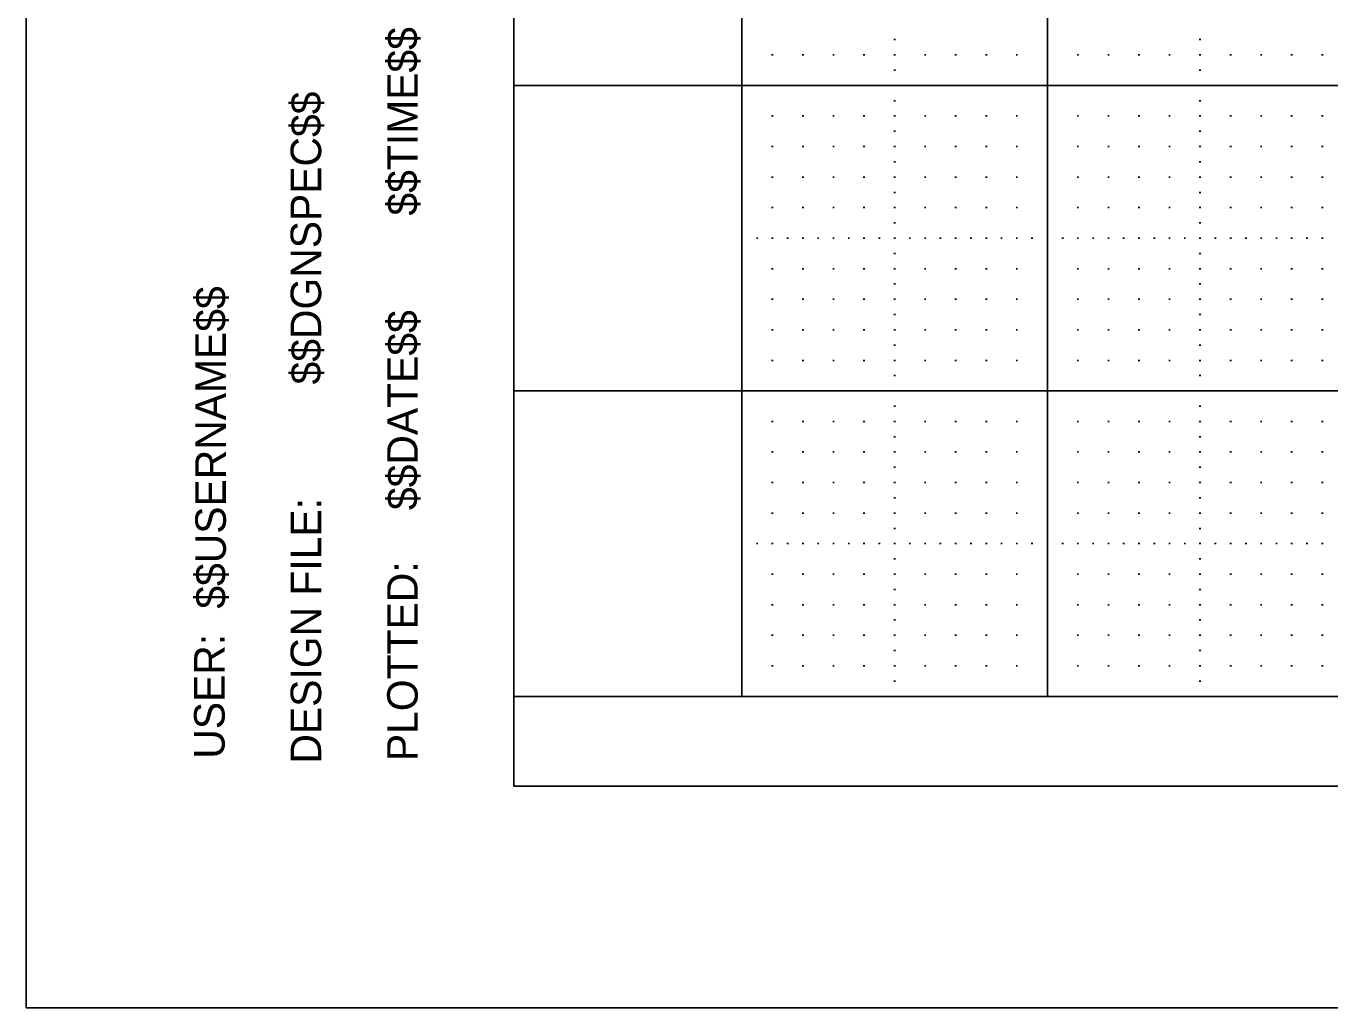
# Model space of a CAD drawing. Extents: x -1.6 to 32.7, y -1.7 to 21.9.
# Drawn here: x -1.598 to 2.67, y -0.727 to 2.487 of the extents above; entities that cross this region are included whole.
import ezdxf

# ---------------------------------------------------------------- set-up
doc = ezdxf.new("R2010")
doc.units = 0
for name, color, linetype in [('Level 1', 7, 'Continuous'), ('Level 4', 7, 'Continuous'), ('Level 5', 7, 'Continuous'), ('Level 63', 7, 'Continuous'), ('R_Border_Dark', 7, 'Continuous')]:
    doc.layers.add(name, color=color, linetype=linetype)

msp = doc.modelspace()

# ---------------------------------------------------------------- linework, layer by layer
at = {"layer": 'Level 1'}
for p, q in [((-0.001, -0.001), (-0.001, 20.545)), ((31.617, -0.001), (-0.001, -0.001))]:
    msp.add_line(p, q, dxfattribs=at)
msp.add_lwpolyline([(0.745, 11.3072), (30.745, 11.3072), (30.745, 0.293), (0.745, 0.293)], close=True, dxfattribs=at)
at = {"layer": 'Level 4'}
msp.add_line((31.617, 0.293), (-0.001, 0.293), dxfattribs=at)
at = {"layer": 'Level 5'}
for p, q in [((1.2425, 2.443), (1.2475, 2.443)), ((2.2425, 2.443), (2.2475, 2.443)), ((0.8425, 2.393), (0.8475, 2.393)), ((0.9425, 2.393), (0.9475, 2.393)), ((1.0425, 2.393), (1.0475, 2.393)), ((1.1425, 2.393), (1.1475, 2.393)), ((1.2425, 2.393), (1.2475, 2.393)), ((1.3425, 2.393), (1.3475, 2.393)), ((1.4425, 2.393), (1.4475, 2.393)), ((1.5425, 2.393), (1.5475, 2.393)), ((1.6425, 2.393), (1.6475, 2.393)), ((1.8425, 2.393), (1.8475, 2.393)), ((1.9425, 2.393), (1.9475, 2.393)), ((2.0425, 2.393), (2.0475, 2.393)), ((2.1425, 2.393), (2.1475, 2.393)), ((2.2425, 2.393), (2.2475, 2.393)), ((2.3425, 2.393), (2.3475, 2.393)), ((2.4425, 2.393), (2.4475, 2.393)), ((2.5425, 2.393), (2.5475, 2.393)), ((2.6425, 2.393), (2.6475, 2.393)), ((1.2425, 2.343), (1.2475, 2.343)), ((2.2425, 2.343), (2.2475, 2.343)), ((1.2425, 2.243), (1.2475, 2.243)), ((2.2425, 2.243), (2.2475, 2.243)), ((0.8425, 2.193), (0.8475, 2.193)), ((0.9425, 2.193), (0.9475, 2.193)), ((1.0425, 2.193), (1.0475, 2.193)), ((1.1425, 2.193), (1.1475, 2.193)), ((1.2425, 2.193), (1.2475, 2.193)), ((1.3425, 2.193), (1.3475, 2.193)), ((1.4425, 2.193), (1.4475, 2.193)), ((1.5425, 2.193), (1.5475, 2.193)), ((1.6425, 2.193), (1.6475, 2.193)), ((1.8425, 2.193), (1.8475, 2.193)), ((1.9425, 2.193), (1.9475, 2.193)), ((2.0425, 2.193), (2.0475, 2.193)), ((2.1425, 2.193), (2.1475, 2.193)), ((2.2425, 2.193), (2.2475, 2.193)), ((2.3425, 2.193), (2.3475, 2.193)), ((2.4425, 2.193), (2.4475, 2.193)), ((2.5425, 2.193), (2.5475, 2.193)), ((2.6425, 2.193), (2.6475, 2.193)), ((1.2425, 2.143), (1.2475, 2.143)), ((2.2425, 2.143), (2.2475, 2.143)), ((0.8425, 2.093), (0.8475, 2.093)), ((0.9425, 2.093), (0.9475, 2.093)), ((1.0425, 2.093), (1.0475, 2.093)), ((1.1425, 2.093), (1.1475, 2.093)), ((1.2425, 2.093), (1.2475, 2.093)), ((1.3425, 2.093), (1.3475, 2.093)), ((1.4425, 2.093), (1.4475, 2.093)), ((1.5425, 2.093), (1.5475, 2.093)), ((1.6425, 2.093), (1.6475, 2.093)), ((1.8425, 2.093), (1.8475, 2.093)), ((1.9425, 2.093), (1.9475, 2.093)), ((2.0425, 2.093), (2.0475, 2.093)), ((2.1425, 2.093), (2.1475, 2.093)), ((2.2425, 2.093), (2.2475, 2.093)), ((2.3425, 2.093), (2.3475, 2.093)), ((2.4425, 2.093), (2.4475, 2.093)), ((2.5425, 2.093), (2.5475, 2.093)), ((2.6425, 2.093), (2.6475, 2.093)), ((1.2425, 2.043), (1.2475, 2.043)), ((2.2425, 2.043), (2.2475, 2.043)), ((0.8425, 1.993), (0.8475, 1.993)), ((0.9425, 1.993), (0.9475, 1.993)), ((1.0425, 1.993), (1.0475, 1.993)), ((1.1425, 1.993), (1.1475, 1.993)), ((1.2425, 1.993), (1.2475, 1.993)), ((1.3425, 1.993), (1.3475, 1.993)), ((1.4425, 1.993), (1.4475, 1.993)), ((1.5425, 1.993), (1.5475, 1.993)), ((1.6425, 1.993), (1.6475, 1.993)), ((1.8425, 1.993), (1.8475, 1.993)), ((1.9425, 1.993), (1.9475, 1.993)), ((2.0425, 1.993), (2.0475, 1.993)), ((2.1425, 1.993), (2.1475, 1.993)), ((2.2425, 1.993), (2.2475, 1.993)), ((2.3425, 1.993), (2.3475, 1.993)), ((2.4425, 1.993), (2.4475, 1.993)), ((2.5425, 1.993), (2.5475, 1.993)), ((2.6425, 1.993), (2.6475, 1.993)), ((1.2425, 1.943), (1.2475, 1.943)), ((2.2425, 1.943), (2.2475, 1.943)), ((0.8425, 1.893), (0.8475, 1.893)), ((0.9425, 1.893), (0.9475, 1.893)), ((1.0425, 1.893), (1.0475, 1.893)), ((1.1425, 1.893), (1.1475, 1.893)), ((1.2425, 1.893), (1.2475, 1.893)), ((1.3425, 1.893), (1.3475, 1.893)), ((1.4425, 1.893), (1.4475, 1.893)), ((1.5425, 1.893), (1.5475, 1.893)), ((1.6425, 1.893), (1.6475, 1.893)), ((1.8425, 1.893), (1.8475, 1.893)), ((1.9425, 1.893), (1.9475, 1.893)), ((2.0425, 1.893), (2.0475, 1.893)), ((2.1425, 1.893), (2.1475, 1.893)), ((2.2425, 1.893), (2.2475, 1.893)), ((2.3425, 1.893), (2.3475, 1.893)), ((2.4425, 1.893), (2.4475, 1.893)), ((2.5425, 1.893), (2.5475, 1.893)), ((2.6425, 1.893), (2.6475, 1.893)), ((1.2425, 1.843), (1.2475, 1.843)), ((2.2425, 1.843), (2.2475, 1.843)), ((0.7925, 1.793), (0.7975, 1.793)), ((0.8425, 1.793), (0.8475, 1.793)), ((0.8925, 1.793), (0.8975, 1.793)), ((0.9425, 1.793), (0.9475, 1.793)), ((0.9925, 1.793), (0.9975, 1.793)), ((1.0425, 1.793), (1.0475, 1.793)), ((1.0925, 1.793), (1.0975, 1.793)), ((1.1425, 1.793), (1.1475, 1.793)), ((1.1925, 1.793), (1.1975, 1.793)), ((1.2425, 1.793), (1.2475, 1.793)), ((1.2925, 1.793), (1.2975, 1.793)), ((1.3425, 1.793), (1.3475, 1.793)), ((1.3925, 1.793), (1.3975, 1.793)), ((1.4425, 1.793), (1.4475, 1.793)), ((1.4925, 1.793), (1.4975, 1.793)), ((1.5425, 1.793), (1.5475, 1.793)), ((1.5925, 1.793), (1.5975, 1.793)), ((1.6425, 1.793), (1.6475, 1.793)), ((1.6925, 1.793), (1.6975, 1.793)), ((1.7925, 1.793), (1.7975, 1.793)), ((1.8425, 1.793), (1.8475, 1.793)), ((1.8925, 1.793), (1.8975, 1.793)), ((1.9425, 1.793), (1.9475, 1.793)), ((1.9925, 1.793), (1.9975, 1.793)), ((2.0425, 1.793), (2.0475, 1.793)), ((2.0925, 1.793), (2.0975, 1.793)), ((2.1425, 1.793), (2.1475, 1.793)), ((2.1925, 1.793), (2.1975, 1.793)), ((2.2425, 1.793), (2.2475, 1.793)), ((2.2925, 1.793), (2.2975, 1.793)), ((2.3425, 1.793), (2.3475, 1.793)), ((2.3925, 1.793), (2.3975, 1.793)), ((2.4425, 1.793), (2.4475, 1.793)), ((2.4925, 1.793), (2.4975, 1.793)), ((2.5425, 1.793), (2.5475, 1.793)), ((2.5925, 1.793), (2.5975, 1.793)), ((2.6425, 1.793), (2.6475, 1.793)), ((1.2425, 1.743), (1.2475, 1.743)), ((2.2425, 1.743), (2.2475, 1.743)), ((0.8425, 1.693), (0.8475, 1.693)), ((0.9425, 1.693), (0.9475, 1.693)), ((1.0425, 1.693), (1.0475, 1.693)), ((1.1425, 1.693), (1.1475, 1.693)), ((1.2425, 1.693), (1.2475, 1.693)), ((1.3425, 1.693), (1.3475, 1.693)), ((1.4425, 1.693), (1.4475, 1.693)), ((1.5425, 1.693), (1.5475, 1.693)), ((1.6425, 1.693), (1.6475, 1.693)), ((1.8425, 1.693), (1.8475, 1.693)), ((1.9425, 1.693), (1.9475, 1.693)), ((2.0425, 1.693), (2.0475, 1.693)), ((2.1425, 1.693), (2.1475, 1.693)), ((2.2425, 1.693), (2.2475, 1.693)), ((2.3425, 1.693), (2.3475, 1.693)), ((2.4425, 1.693), (2.4475, 1.693)), ((2.5425, 1.693), (2.5475, 1.693)), ((2.6425, 1.693), (2.6475, 1.693)), ((1.2425, 1.643), (1.2475, 1.643)), ((2.2425, 1.643), (2.2475, 1.643)), ((0.8425, 1.593), (0.8475, 1.593)), ((0.9425, 1.593), (0.9475, 1.593)), ((1.0425, 1.593), (1.0475, 1.593)), ((1.1425, 1.593), (1.1475, 1.593)), ((1.2425, 1.593), (1.2475, 1.593)), ((1.3425, 1.593), (1.3475, 1.593)), ((1.4425, 1.593), (1.4475, 1.593)), ((1.5425, 1.593), (1.5475, 1.593)), ((1.6425, 1.593), (1.6475, 1.593)), ((1.8425, 1.593), (1.8475, 1.593)), ((1.9425, 1.593), (1.9475, 1.593)), ((2.0425, 1.593), (2.0475, 1.593)), ((2.1425, 1.593), (2.1475, 1.593)), ((2.2425, 1.593), (2.2475, 1.593)), ((2.3425, 1.593), (2.3475, 1.593)), ((2.4425, 1.593), (2.4475, 1.593)), ((2.5425, 1.593), (2.5475, 1.593)), ((2.6425, 1.593), (2.6475, 1.593)), ((1.2425, 1.543), (1.2475, 1.543)), ((2.2425, 1.543), (2.2475, 1.543)), ((0.8425, 1.493), (0.8475, 1.493)), ((0.9425, 1.493), (0.9475, 1.493)), ((1.0425, 1.493), (1.0475, 1.493)), ((1.1425, 1.493), (1.1475, 1.493)), ((1.2425, 1.493), (1.2475, 1.493)), ((1.3425, 1.493), (1.3475, 1.493)), ((1.4425, 1.493), (1.4475, 1.493)), ((1.5425, 1.493), (1.5475, 1.493)), ((1.6425, 1.493), (1.6475, 1.493)), ((1.8425, 1.493), (1.8475, 1.493)), ((1.9425, 1.493), (1.9475, 1.493)), ((2.0425, 1.493), (2.0475, 1.493)), ((2.1425, 1.493), (2.1475, 1.493)), ((2.2425, 1.493), (2.2475, 1.493)), ((2.3425, 1.493), (2.3475, 1.493)), ((2.4425, 1.493), (2.4475, 1.493)), ((2.5425, 1.493), (2.5475, 1.493)), ((2.6425, 1.493), (2.6475, 1.493)), ((1.2425, 1.443), (1.2475, 1.443)), ((2.2425, 1.443), (2.2475, 1.443)), ((0.8425, 1.393), (0.8475, 1.393)), ((0.9425, 1.393), (0.9475, 1.393)), ((1.0425, 1.393), (1.0475, 1.393)), ((1.1425, 1.393), (1.1475, 1.393)), ((1.2425, 1.393), (1.2475, 1.393)), ((1.3425, 1.393), (1.3475, 1.393)), ((1.4425, 1.393), (1.4475, 1.393)), ((1.5425, 1.393), (1.5475, 1.393)), ((1.6425, 1.393), (1.6475, 1.393)), ((1.8425, 1.393), (1.8475, 1.393)), ((1.9425, 1.393), (1.9475, 1.393)), ((2.0425, 1.393), (2.0475, 1.393)), ((2.1425, 1.393), (2.1475, 1.393)), ((2.2425, 1.393), (2.2475, 1.393)), ((2.3425, 1.393), (2.3475, 1.393)), ((2.4425, 1.393), (2.4475, 1.393)), ((2.5425, 1.393), (2.5475, 1.393)), ((2.6425, 1.393), (2.6475, 1.393)), ((1.2425, 1.343), (1.2475, 1.343)), ((2.2425, 1.343), (2.2475, 1.343)), ((1.2425, 1.243), (1.2475, 1.243)), ((2.2425, 1.243), (2.2475, 1.243)), ((0.8425, 1.193), (0.8475, 1.193)), ((0.9425, 1.193), (0.9475, 1.193)), ((1.0425, 1.193), (1.0475, 1.193)), ((1.1425, 1.193), (1.1475, 1.193)), ((1.2425, 1.193), (1.2475, 1.193)), ((1.3425, 1.193), (1.3475, 1.193)), ((1.4425, 1.193), (1.4475, 1.193)), ((1.5425, 1.193), (1.5475, 1.193)), ((1.6425, 1.193), (1.6475, 1.193)), ((1.8425, 1.193), (1.8475, 1.193)), ((1.9425, 1.193), (1.9475, 1.193)), ((2.0425, 1.193), (2.0475, 1.193)), ((2.1425, 1.193), (2.1475, 1.193)), ((2.2425, 1.193), (2.2475, 1.193)), ((2.3425, 1.193), (2.3475, 1.193)), ((2.4425, 1.193), (2.4475, 1.193)), ((2.5425, 1.193), (2.5475, 1.193)), ((2.6425, 1.193), (2.6475, 1.193)), ((1.2425, 1.143), (1.2475, 1.143)), ((2.2425, 1.143), (2.2475, 1.143)), ((0.8425, 1.093), (0.8475, 1.093)), ((0.9425, 1.093), (0.9475, 1.093)), ((1.0425, 1.093), (1.0475, 1.093)), ((1.1425, 1.093), (1.1475, 1.093)), ((1.2425, 1.093), (1.2475, 1.093)), ((1.3425, 1.093), (1.3475, 1.093)), ((1.4425, 1.093), (1.4475, 1.093)), ((1.5425, 1.093), (1.5475, 1.093)), ((1.6425, 1.093), (1.6475, 1.093)), ((1.8425, 1.093), (1.8475, 1.093)), ((1.9425, 1.093), (1.9475, 1.093)), ((2.0425, 1.093), (2.0475, 1.093)), ((2.1425, 1.093), (2.1475, 1.093)), ((2.2425, 1.093), (2.2475, 1.093)), ((2.3425, 1.093), (2.3475, 1.093)), ((2.4425, 1.093), (2.4475, 1.093)), ((2.5425, 1.093), (2.5475, 1.093)), ((2.6425, 1.093), (2.6475, 1.093)), ((1.2425, 1.043), (1.2475, 1.043)), ((2.2425, 1.043), (2.2475, 1.043)), ((0.8425, 0.993), (0.8475, 0.993)), ((0.9425, 0.993), (0.9475, 0.993)), ((1.0425, 0.993), (1.0475, 0.993)), ((1.1425, 0.993), (1.1475, 0.993)), ((1.2425, 0.993), (1.2475, 0.993)), ((1.3425, 0.993), (1.3475, 0.993)), ((1.4425, 0.993), (1.4475, 0.993)), ((1.5425, 0.993), (1.5475, 0.993)), ((1.6425, 0.993), (1.6475, 0.993)), ((1.8425, 0.993), (1.8475, 0.993)), ((1.9425, 0.993), (1.9475, 0.993)), ((2.0425, 0.993), (2.0475, 0.993)), ((2.1425, 0.993), (2.1475, 0.993)), ((2.2425, 0.993), (2.2475, 0.993)), ((2.3425, 0.993), (2.3475, 0.993)), ((2.4425, 0.993), (2.4475, 0.993)), ((2.5425, 0.993), (2.5475, 0.993)), ((2.6425, 0.993), (2.6475, 0.993)), ((1.2425, 0.943), (1.2475, 0.943)), ((2.2425, 0.943), (2.2475, 0.943)), ((0.8425, 0.893), (0.8475, 0.893)), ((0.9425, 0.893), (0.9475, 0.893)), ((1.0425, 0.893), (1.0475, 0.893)), ((1.1425, 0.893), (1.1475, 0.893)), ((1.2425, 0.893), (1.2475, 0.893)), ((1.3425, 0.893), (1.3475, 0.893)), ((1.4425, 0.893), (1.4475, 0.893)), ((1.5425, 0.893), (1.5475, 0.893)), ((1.6425, 0.893), (1.6475, 0.893)), ((1.8425, 0.893), (1.8475, 0.893)), ((1.9425, 0.893), (1.9475, 0.893)), ((2.0425, 0.893), (2.0475, 0.893)), ((2.1425, 0.893), (2.1475, 0.893)), ((2.2425, 0.893), (2.2475, 0.893)), ((2.3425, 0.893), (2.3475, 0.893)), ((2.4425, 0.893), (2.4475, 0.893)), ((2.5425, 0.893), (2.5475, 0.893)), ((2.6425, 0.893), (2.6475, 0.893)), ((1.2425, 0.843), (1.2475, 0.843)), ((2.2425, 0.843), (2.2475, 0.843)), ((0.7925, 0.793), (0.7975, 0.793)), ((0.8425, 0.793), (0.8475, 0.793)), ((0.8925, 0.793), (0.8975, 0.793)), ((0.9425, 0.793), (0.9475, 0.793)), ((0.9925, 0.793), (0.9975, 0.793)), ((1.0425, 0.793), (1.0475, 0.793)), ((1.0925, 0.793), (1.0975, 0.793)), ((1.1425, 0.793), (1.1475, 0.793)), ((1.1925, 0.793), (1.1975, 0.793)), ((1.2425, 0.793), (1.2475, 0.793)), ((1.2925, 0.793), (1.2975, 0.793)), ((1.3425, 0.793), (1.3475, 0.793)), ((1.3925, 0.793), (1.3975, 0.793)), ((1.4425, 0.793), (1.4475, 0.793)), ((1.4925, 0.793), (1.4975, 0.793)), ((1.5425, 0.793), (1.5475, 0.793)), ((1.5925, 0.793), (1.5975, 0.793)), ((1.6425, 0.793), (1.6475, 0.793)), ((1.6925, 0.793), (1.6975, 0.793)), ((1.7925, 0.793), (1.7975, 0.793)), ((1.8425, 0.793), (1.8475, 0.793)), ((1.8925, 0.793), (1.8975, 0.793)), ((1.9425, 0.793), (1.9475, 0.793)), ((1.9925, 0.793), (1.9975, 0.793)), ((2.0425, 0.793), (2.0475, 0.793)), ((2.0925, 0.793), (2.0975, 0.793)), ((2.1425, 0.793), (2.1475, 0.793)), ((2.1925, 0.793), (2.1975, 0.793)), ((2.2425, 0.793), (2.2475, 0.793)), ((2.2925, 0.793), (2.2975, 0.793)), ((2.3425, 0.793), (2.3475, 0.793)), ((2.3925, 0.793), (2.3975, 0.793)), ((2.4425, 0.793), (2.4475, 0.793)), ((2.4925, 0.793), (2.4975, 0.793)), ((2.5425, 0.793), (2.5475, 0.793)), ((2.5925, 0.793), (2.5975, 0.793)), ((2.6425, 0.793), (2.6475, 0.793)), ((1.2425, 0.743), (1.2475, 0.743)), ((2.2425, 0.743), (2.2475, 0.743)), ((0.8425, 0.693), (0.8475, 0.693)), ((0.9425, 0.693), (0.9475, 0.693)), ((1.0425, 0.693), (1.0475, 0.693)), ((1.1425, 0.693), (1.1475, 0.693)), ((1.2425, 0.693), (1.2475, 0.693)), ((1.3425, 0.693), (1.3475, 0.693)), ((1.4425, 0.693), (1.4475, 0.693)), ((1.5425, 0.693), (1.5475, 0.693)), ((1.6425, 0.693), (1.6475, 0.693)), ((1.8425, 0.693), (1.8475, 0.693)), ((1.9425, 0.693), (1.9475, 0.693)), ((2.0425, 0.693), (2.0475, 0.693)), ((2.1425, 0.693), (2.1475, 0.693)), ((2.2425, 0.693), (2.2475, 0.693)), ((2.3425, 0.693), (2.3475, 0.693)), ((2.4425, 0.693), (2.4475, 0.693)), ((2.5425, 0.693), (2.5475, 0.693)), ((2.6425, 0.693), (2.6475, 0.693)), ((1.2425, 0.643), (1.2475, 0.643)), ((2.2425, 0.643), (2.2475, 0.643)), ((0.8425, 0.593), (0.8475, 0.593)), ((0.9425, 0.593), (0.9475, 0.593)), ((1.0425, 0.593), (1.0475, 0.593)), ((1.1425, 0.593), (1.1475, 0.593)), ((1.2425, 0.593), (1.2475, 0.593)), ((1.3425, 0.593), (1.3475, 0.593)), ((1.4425, 0.593), (1.4475, 0.593)), ((1.5425, 0.593), (1.5475, 0.593)), ((1.6425, 0.593), (1.6475, 0.593)), ((1.8425, 0.593), (1.8475, 0.593)), ((1.9425, 0.593), (1.9475, 0.593)), ((2.0425, 0.593), (2.0475, 0.593)), ((2.1425, 0.593), (2.1475, 0.593)), ((2.2425, 0.593), (2.2475, 0.593)), ((2.3425, 0.593), (2.3475, 0.593)), ((2.4425, 0.593), (2.4475, 0.593)), ((2.5425, 0.593), (2.5475, 0.593)), ((2.6425, 0.593), (2.6475, 0.593)), ((1.2425, 0.543), (1.2475, 0.543)), ((2.2425, 0.543), (2.2475, 0.543)), ((0.8425, 0.493), (0.8475, 0.493)), ((0.9425, 0.493), (0.9475, 0.493)), ((1.0425, 0.493), (1.0475, 0.493)), ((1.1425, 0.493), (1.1475, 0.493)), ((1.2425, 0.493), (1.2475, 0.493)), ((1.3425, 0.493), (1.3475, 0.493)), ((1.4425, 0.493), (1.4475, 0.493)), ((1.5425, 0.493), (1.5475, 0.493)), ((1.6425, 0.493), (1.6475, 0.493)), ((1.8425, 0.493), (1.8475, 0.493)), ((1.9425, 0.493), (1.9475, 0.493)), ((2.0425, 0.493), (2.0475, 0.493)), ((2.1425, 0.493), (2.1475, 0.493)), ((2.2425, 0.493), (2.2475, 0.493)), ((2.3425, 0.493), (2.3475, 0.493)), ((2.4425, 0.493), (2.4475, 0.493)), ((2.5425, 0.493), (2.5475, 0.493)), ((2.6425, 0.493), (2.6475, 0.493)), ((1.2425, 0.443), (1.2475, 0.443)), ((2.2425, 0.443), (2.2475, 0.443)), ((0.8425, 0.393), (0.8475, 0.393)), ((0.9425, 0.393), (0.9475, 0.393)), ((1.0425, 0.393), (1.0475, 0.393)), ((1.1425, 0.393), (1.1475, 0.393)), ((1.2425, 0.393), (1.2475, 0.393)), ((1.3425, 0.393), (1.3475, 0.393)), ((1.4425, 0.393), (1.4475, 0.393)), ((1.5425, 0.393), (1.5475, 0.393)), ((1.6425, 0.393), (1.6475, 0.393)), ((1.8425, 0.393), (1.8475, 0.393)), ((1.9425, 0.393), (1.9475, 0.393)), ((2.0425, 0.393), (2.0475, 0.393)), ((2.1425, 0.393), (2.1475, 0.393)), ((2.2425, 0.393), (2.2475, 0.393)), ((2.3425, 0.393), (2.3475, 0.393)), ((2.4425, 0.393), (2.4475, 0.393)), ((2.5425, 0.393), (2.5475, 0.393)), ((2.6425, 0.393), (2.6475, 0.393)), ((1.2425, 0.343), (1.2475, 0.343)), ((2.2425, 0.343), (2.2475, 0.343))]:
    msp.add_line(p, q, dxfattribs=at)
at = {"layer": 'Level 63'}
msp.add_lwpolyline([(-1.598, -0.727), (32.402, -0.727), (32.402, 21.273), (-1.598, 21.273)], close=True, dxfattribs=at)
msp.add_lwpolyline([(30.745, 8.293), (30.745, 0.293), (0.745, 0.293), (0.745, 8.293)], dxfattribs=at)
at = {"layer": 'R_Border_Dark'}
for p, q in [((1.745, 0.293), (1.745, 11.3072)), ((0.745, 0.293), (0.745, 8.293)), ((31.617, 2.293), (-0.001, 2.293)), ((31.617, 1.293), (-0.001, 1.293))]:
    msp.add_line(p, q, dxfattribs=at)
msp.add_lwpolyline([(30.745, 8.293), (30.745, 0.293), (0.745, 0.293), (0.745, 8.293)], dxfattribs=at)

# ---------------------------------------------------------------- texts
at = {"layer": 'Level 1'}
for s, height, p in [('$$TIME$$', 0.1, (-0.316, 1.867)), ('$$DGNSPEC$$', 0.100002, (-0.632, 1.314)), ('$$USERNAME$$', 0.100002, (-0.944, 0.58)), ('$$DATE$$', 0.1, (-0.316, 0.903)), ('DESIGN FILE:', 0.100002, (-0.632, 0.073)), ('PLOTTED:', 0.1, (-0.316, 0.081)), ('USER:', 0.1, (-0.948, 0.089))]:
    msp.add_text(s, height=height, rotation=90, dxfattribs=at).set_placement(p)

doc.saveas('drawing.dxf')
